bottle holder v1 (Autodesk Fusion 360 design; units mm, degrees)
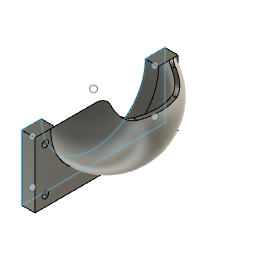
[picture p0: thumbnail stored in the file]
sketch "Sketch1" plane through (0, 0, 0) normal (1, 0, 0) x axis (0, 1, 0)
  line L1 (-15, 25) -> (-30, 25)
  line L2 (-125, 25) -> (-110, 25)
  line L3 (-125, -25) -> (-125, 25)
  line L4 (-15, -25) -> (-125, -25)
  line L5 (-15, 25) -> (-15, -25)
  arc A1 centre (-70, 25) radius 40 clockwise from (-30, 25) to (-110, 25)
  circle C1 centre (-117, 17) radius 1.5
  circle C2 centre (-117, -17) radius 1.5
  circle C3 centre (-23, 17) radius 1.5
  circle C4 centre (-23, -17) radius 1.5
  point P2 (-30, 25)
  point P3 (-15, 25)
  point P4 (-110, 25)
  point P5 (-125, 25)
  point P9 (-117, 17)
  point P10 (-117, -17)
  point P11 (-23, 17)
  point P12 (-23, -17)
  point P6 (-125, -25)
  horizontal L1
  horizontal L2
  perpendicular L2 L3
  perpendicular L3 L4
  perpendicular L1 L5
  dimension "d2" distance P2 P3 = 15
  dimension "d3" distance P4 P5 = 15
  dimension "d9" diameter C1 = 3
  dimension "d15" diameter C2 = 3
  dimension "d16" distance L3 P9 = 8
  dimension "d17" distance L2 P9 = 8
  dimension "d18" distance L4 P10 = 8
  dimension "d19" distance L3 P10 = 8
  dimension "d20" diameter C3 = 3
  dimension "d21" diameter C4 = 3
  dimension "d22" distance L5 P11 = 8
  dimension "d23" distance L5 P12 = 8
  dimension "d52" distance P5 P6 = 50
extrude "Extrude2" new body sketch "Sketch1" along normal blind 10
extrude "Extrude1" new body sketch "Sketch1" profile of L1 L2 L3 L4 L5 A1 along normal blind 10
extrude "Extrude3" cut sketch "Sketch1" profile of C3 along normal blind 10
extrude "Extrude4" cut sketch "Sketch1" profile of C1 C2 C4 along normal blind 10
sketch "Sketch2" plane through (10, 0, 0) normal (1, 0, 0) x axis (0, 1, 0)
  line L1 (-125, -25) -> (-125, 25)
  line L2 (-15, -25) -> (-125, -25)
  line L3 (-15, 25) -> (-15, -25)
  line L4 (-30, 25) -> (-15, 25)
  line L5 (-125, 25) -> (-110, 25)
  line L6 (-113, 25) -> (-110, 25)
  line L7 (-27, 25) -> (-30, 25)
  circle C1 centre (-23, -17) radius 1.5
  circle C2 centre (-117, -17) radius 1.5
  circle C3 centre (-117, 17) radius 1.5
  circle C4 centre (-23, 17) radius 1.5
  arc A1 centre (-70, 25) radius 40 clockwise from (-30, 25) to (-110, 25)
  arc A2 centre (-70, 25) radius 40 clockwise from (-30, 25) to (-110, 25)
  arc A3 centre (-70, 25) radius 43 clockwise from (-27, 25) to (-113, 25)
  point P10 (-30, 25)
  point P15 (-30, 25)
  point P11 (-110, 25)
  point P14 (-110, 25)
  point P12 (-70, 25)
  point P13 (-70, 25)
  point P16 (-110, 25)
  point P18 (-30, 25)
  point P20 (-70, 25)
  point P17 (-113, 25)
  point P19 (-27, 25)
  coincident P10 P15
  coincident P11 P14
  coincident P12 P13
  coincident P11 P16
  parallel L5 L6
  coincident P10 P18
  parallel L4 L7
  coincident P12 P20
  dimension "d30" distance P16 P17 = 3
  dimension "d31" distance P18 P19 = 3
revolve "Revolve1" sketch "Sketch2" AlongAngle 135
sketch "Sketch3" plane through (0, -70, 0) normal (1, 0, 0) x axis (0, 1, 0)
  line L1 (-25, 56) -> (25, 56)
  line L2 (25, 46) -> (25, 56)
  line L3 (-15, 36) -> (15, 36)
  line L4 (-25, 56) -> (-25, 46)
  arc A1 centre (15, 46) radius 10 clockwise from (25, 46) to (15, 36)
  arc A2 centre (-15, 46) radius 10 clockwise from (-15, 36) to (-25, 46)
  point P5 (25, 36)
  point P2 (25, 56)
  point P4 (40, 25)
  point P3 (-25, 56)
  horizontal L1
  perpendicular L1 L2
  perpendicular L2 L3
  perpendicular L1 L4
  coincident P5 L2
  coincident P5 L3
  tangent L2 A1
  tangent L3 A1
  tangent L3 A2
  tangent L4 A2
  dimension "d34" distance P2 P4 = 15
  dimension "d35" distance P2 P3 = 50
  dimension "d36" distance L1 P4 = 31
  dimension "d37" distance P2 P5 = 20
  dimension "d38" radius A1 = 10
  dimension "d39" radius A2 = 10
extrude "Extrude5" cut sketch "Sketch3" along normal blind 52
fillet "Fillet1" radius 5
fillet "Fillet2" radius 5
sketch "Sketch4" plane through (10, 0, 0) normal (1, 0, 0) x axis (0, 1, 0)
  line L1 (-125, 25) -> (-113, 25)
  line L2 (-125, -25) -> (-125, 25)
  line L3 (-15, -25) -> (-125, -25)
  line L4 (-15, 25) -> (-15, -25)
  line L5 (-27, 25) -> (-15, 25)
  arc A1 centre (-70, 25) radius 43 clockwise from (-27, 25) to (-113, 25)
  circle C1 centre (-23, 17) radius 1.5
  circle C2 centre (-23, -17) radius 1.5
  circle C3 centre (-117, 17) radius 1.5
  circle C4 centre (-117, -17) radius 1.5
  circle C5 centre (-23, 17) radius 2.5
  circle C6 centre (-23, -17) radius 2.5
  circle C7 centre (-117, -17) radius 2.5
  circle C8 centre (-117, 17) radius 2.5
  concentric C1 C5
  concentric C2 C6
  concentric C4 C7
  concentric C3 C8
  dimension "d44" diameter C5 = 5
  dimension "d45" diameter C6 = 5
  dimension "d46" diameter C7 = 5
  dimension "d47" diameter C8 = 5
extrude "Extrude6" cut sketch "Sketch4" profile of C1 C2 C3 C4 C5 C6 C7 C8 against normal blind 4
